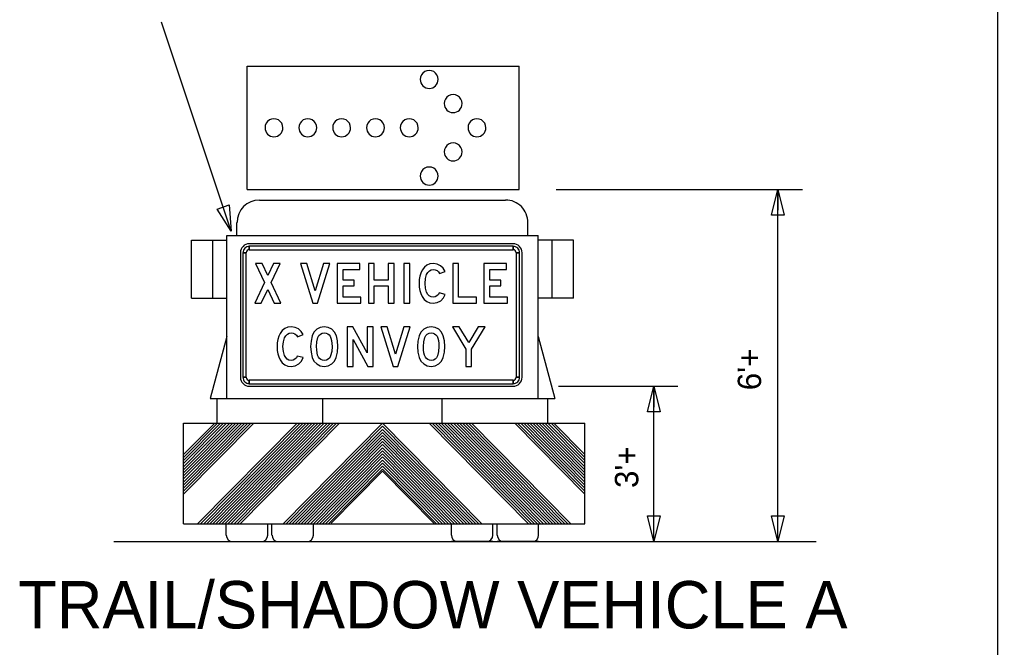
# Model space of a CAD drawing. Extents: x 1416408 to 1429341, y 372694 to 383211.
# Drawn here: x 1427683.6 to 1428099.1, y 374030.4 to 374297 of the extents above; entities that cross this region are included whole.
import ezdxf

# ---------------------------------------------------------------- set-up
doc = ezdxf.new("R2010")
doc.units = 0
doc.layers.add('Working Level 1', color=7, linetype='Continuous')

msp = doc.modelspace()

# ---------------------------------------------------------------- linework, layer by layer
at = {"layer": 'Working Level 1'}
for p, q in [((1428099.08, 374447.3), (1428099.08, 372727.17)), ((1427773.53, 374207.09), (1427743.96, 374295.96)), ((1427780.31, 374277.25), (1427895.86, 374277.25)), ((1427780.31, 374224.87), (1427780.31, 374277.25)), ((1427895.86, 374224.87), (1427895.86, 374277.25)), ((1427780.31, 374224.87), (1427895.86, 374224.87)), ((1427911.54, 374224.87), (1428016.33, 374224.87)), ((1428005.79, 374075.32), (1428005.79, 374224.87)), ((1428005.79, 374224.87), (1428005.79, 374216.1)), ((1427785.52, 374220.38), (1427890.09, 374220.38)), ((1427776.01, 374205.26), (1427776.01, 374210.78)), ((1427899.6, 374205.26), (1427899.6, 374210.78)), ((1427771.7, 374136.16), (1427771.7, 374205.26)), ((1427771.7, 374205.26), (1427903.91, 374205.26)), ((1427903.91, 374136.16), (1427903.91, 374205.26)), ((1427756.62, 374178.75), (1427756.62, 374203.31)), ((1427756.62, 374203.31), (1427771.7, 374203.31)), ((1427765.75, 374178.75), (1427765.75, 374203.31)), ((1427893.36, 374201.79), (1427781.21, 374201.79)), ((1427918.99, 374203.31), (1427903.91, 374203.31)), ((1427909.85, 374178.75), (1427909.85, 374203.31)), ((1427918.99, 374178.75), (1427918.99, 374203.31)), ((1427777.48, 374198.01), (1427777.48, 374145.1)), ((1427778.51, 374198.01), (1427779.97, 374198.01)), ((1427781.21, 374199.27), (1427781.21, 374200.74)), ((1427893.36, 374200.74), (1427893.36, 374199.27)), ((1427894.6, 374198.01), (1427896.06, 374198.01)), ((1427897.1, 374145.1), (1427897.1, 374198.01)), ((1427756.62, 374178.75), (1427771.7, 374178.75)), ((1427918.99, 374178.75), (1427903.91, 374178.75)), ((1427771.7, 374162.48), (1427764.55, 374136.16)), ((1427903.91, 374162.48), (1427911.06, 374136.16)), ((1427779.97, 374145.1), (1427778.51, 374145.1)), ((1427781.21, 374142.37), (1427781.21, 374143.84)), ((1427893.36, 374143.84), (1427893.36, 374142.37)), ((1427896.06, 374145.1), (1427894.6, 374145.1)), ((1427781.21, 374141.32), (1427893.36, 374141.32)), ((1427912.62, 374141.32), (1427963.33, 374141.32)), ((1427953.11, 374075.32), (1427953.11, 374141.32)), ((1427953.11, 374141.32), (1427953.11, 374132.41)), ((1427764.55, 374136.16), (1427911.06, 374136.16)), ((1427767.52, 374125.61), (1427767.52, 374136.16)), ((1427812.44, 374125.61), (1427812.44, 374135.97)), ((1427863.17, 374125.61), (1427863.17, 374135.97)), ((1427908.09, 374125.61), (1427908.09, 374136.16)), ((1427753.33, 374125.61), (1427923.83, 374125.61)), ((1427753.33, 374125.61), (1427923.83, 374125.61)), ((1427753.33, 374125.61), (1427923.83, 374125.61)), ((1427753.33, 374125.61), (1427923.83, 374125.61)), ((1427753.33, 374082.92), (1427753.33, 374125.61)), ((1427753.33, 374112.25), (1427766.55, 374125.61)), ((1427753.33, 374096.71), (1427781.91, 374125.61)), ((1427753.33, 374098.02), (1427780.62, 374125.61)), ((1427753.33, 374099.33), (1427779.33, 374125.61)), ((1427753.33, 374100.62), (1427778.05, 374125.61)), ((1427753.33, 374101.92), (1427776.76, 374125.61)), ((1427753.33, 374103.23), (1427775.46, 374125.61)), ((1427753.33, 374104.52), (1427774.19, 374125.61)), ((1427753.33, 374105.83), (1427772.9, 374125.61)), ((1427753.33, 374107.14), (1427771.6, 374125.61)), ((1427753.33, 374108.44), (1427770.31, 374125.61)), ((1427753.33, 374109.73), (1427769.03, 374125.61)), ((1427753.33, 374111.04), (1427767.74, 374125.61)), ((1427753.33, 374095.41), (1427783.16, 374125.57)), ((1427759.28, 374082.92), (1427801.51, 374125.61)), ((1427760.56, 374082.92), (1427802.79, 374125.61)), ((1427761.86, 374082.92), (1427804.08, 374125.61)), ((1427763.15, 374082.92), (1427805.38, 374125.61)), ((1427764.42, 374082.92), (1427806.65, 374125.61)), ((1427765.72, 374082.92), (1427807.95, 374125.61)), ((1427767.01, 374082.92), (1427809.24, 374125.61)), ((1427768.3, 374082.92), (1427810.53, 374125.61)), ((1427769.58, 374082.92), (1427811.81, 374125.61)), ((1427770.87, 374082.92), (1427813.1, 374125.61)), ((1427772.17, 374082.92), (1427814.39, 374125.61)), ((1427773.44, 374082.92), (1427815.67, 374125.61)), ((1427774.74, 374082.92), (1427816.96, 374125.61)), ((1427776.03, 374082.92), (1427818.24, 374125.59)), ((1427777.31, 374082.92), (1427819.54, 374125.61)), ((1427795.58, 374082.92), (1427837.8, 374125.61)), ((1427796.86, 374082.92), (1427837.8, 374124.31)), ((1427798.15, 374082.92), (1427837.8, 374123)), ((1427880.03, 374082.92), (1427837.8, 374125.61)), ((1427878.68, 374082.99), (1427837.8, 374124.31)), ((1427877.46, 374082.92), (1427837.8, 374123)), ((1427899.84, 374082.92), (1427857.62, 374125.61)), ((1427901.13, 374082.92), (1427858.92, 374125.59)), ((1427902.42, 374082.92), (1427860.19, 374125.61)), ((1427903.72, 374082.92), (1427861.49, 374125.61)), ((1427904.99, 374082.92), (1427862.76, 374125.61)), ((1427906.28, 374082.92), (1427864.06, 374125.61)), ((1427907.58, 374082.92), (1427865.35, 374125.61)), ((1427908.85, 374082.92), (1427866.62, 374125.61)), ((1427910.15, 374082.92), (1427867.92, 374125.61)), ((1427911.44, 374082.92), (1427869.21, 374125.61)), ((1427912.73, 374082.92), (1427870.5, 374125.61)), ((1427914.01, 374082.92), (1427871.78, 374125.61)), ((1427915.3, 374082.92), (1427873.07, 374125.61)), ((1427916.6, 374082.92), (1427874.37, 374125.61)), ((1427917.88, 374082.92), (1427875.65, 374125.61)), ((1427923.83, 374095.41), (1427894, 374125.57)), ((1427923.83, 374096.71), (1427895.24, 374125.61)), ((1427923.83, 374098.02), (1427896.54, 374125.61)), ((1427923.83, 374099.33), (1427897.83, 374125.61)), ((1427923.83, 374100.62), (1427899.11, 374125.61)), ((1427923.83, 374101.92), (1427900.4, 374125.61)), ((1427923.83, 374103.23), (1427901.69, 374125.61)), ((1427923.83, 374104.52), (1427902.97, 374125.61)), ((1427923.83, 374105.83), (1427904.26, 374125.61)), ((1427923.83, 374107.14), (1427905.56, 374125.61)), ((1427923.83, 374108.44), (1427906.85, 374125.61)), ((1427923.83, 374109.73), (1427908.12, 374125.61)), ((1427923.83, 374111.04), (1427909.42, 374125.61)), ((1427923.83, 374112.25), (1427910.61, 374125.61)), ((1427923.83, 374082.92), (1427923.83, 374125.61)), ((1427799.45, 374082.92), (1427837.8, 374121.7)), ((1427800.72, 374082.92), (1427837.8, 374120.41)), ((1427802.02, 374082.92), (1427837.8, 374119.1)), ((1427803.31, 374082.92), (1427837.8, 374117.79)), ((1427876.17, 374082.92), (1427837.8, 374121.7)), ((1427874.9, 374082.92), (1427837.8, 374120.41)), ((1427873.6, 374082.92), (1427837.8, 374119.1)), ((1427872.31, 374082.92), (1427837.8, 374117.79)), ((1427804.58, 374082.92), (1427837.8, 374116.5)), ((1427805.88, 374082.92), (1427837.8, 374115.19)), ((1427807.17, 374082.92), (1427837.8, 374113.89)), ((1427871.03, 374082.92), (1427837.8, 374116.5)), ((1427869.74, 374082.92), (1427837.8, 374115.19)), ((1427868.45, 374082.92), (1427837.8, 374113.89)), ((1427808.46, 374082.92), (1427837.8, 374112.58)), ((1427809.74, 374082.92), (1427837.8, 374111.29)), ((1427811.03, 374082.92), (1427837.8, 374109.98)), ((1427867.15, 374082.92), (1427837.8, 374112.58)), ((1427865.88, 374082.92), (1427837.8, 374111.29)), ((1427864.58, 374082.92), (1427837.8, 374109.98)), ((1427812.33, 374082.92), (1427837.8, 374108.67)), ((1427813.6, 374082.92), (1427837.8, 374107.39)), ((1427814.89, 374082.92), (1427837.8, 374106.09)), ((1427863.29, 374082.92), (1427837.8, 374108.67)), ((1427862.02, 374082.92), (1427837.8, 374107.39)), ((1427860.72, 374082.92), (1427837.8, 374106.09)), ((1427815.97, 374083.16), (1427837.8, 374105.24)), ((1427859.88, 374082.92), (1427837.8, 374105.24)), ((1427753.33, 374082.92), (1427923.83, 374082.92)), ((1427753.33, 374082.92), (1427923.83, 374082.92)), ((1427753.33, 374082.92), (1427923.83, 374082.92)), ((1427753.33, 374082.92), (1427923.83, 374082.92)), ((1427771.45, 374078.08), (1427771.45, 374082.92)), ((1427789.06, 374078.08), (1427789.06, 374082.92)), ((1427790.88, 374078.08), (1427790.88, 374082.92)), ((1427808.5, 374078.08), (1427808.5, 374082.92)), ((1427867.11, 374078.08), (1427867.11, 374082.92)), ((1427884.72, 374078.08), (1427884.72, 374082.92)), ((1427886.55, 374078.08), (1427886.55, 374082.92)), ((1427904.16, 374078.08), (1427904.16, 374082.92)), ((1427723.72, 374075.32), (1428022.01, 374075.32)), ((1427771.45, 374075.32), (1427789.06, 374075.32)), ((1427771.45, 374075.32), (1427789.06, 374075.32)), ((1427771.45, 374075.32), (1427789.06, 374075.32)), ((1427771.45, 374075.32), (1427789.06, 374075.32)), ((1427790.88, 374075.32), (1427808.5, 374075.32)), ((1427790.88, 374075.32), (1427808.5, 374075.32)), ((1427790.88, 374075.32), (1427808.5, 374075.32)), ((1427790.88, 374075.32), (1427808.5, 374075.32)), ((1427884.72, 374075.32), (1427867.11, 374075.32)), ((1427884.72, 374075.32), (1427867.11, 374075.32)), ((1427884.72, 374075.32), (1427867.11, 374075.32)), ((1427884.72, 374075.32), (1427867.11, 374075.32)), ((1427904.16, 374075.32), (1427886.55, 374075.32)), ((1427904.16, 374075.32), (1427886.55, 374075.32)), ((1427904.16, 374075.32), (1427886.55, 374075.32)), ((1427904.16, 374075.32), (1427886.55, 374075.32))]:
    msp.add_line(p, q, dxfattribs=at)
for points in [[(1428003.1, 374213.98), (1428005.79, 374224.87), (1428008.48, 374213.98)], [(1427772.65, 374218.28), (1427773.53, 374207.09), (1427767.55, 374216.54)], [(1427778.51, 374198.01), (1427778.51, 374145.1), (1427779.97, 374145.1), (1427779.97, 374198.01), (1427778.51, 374198.01)], [(1427893.36, 374200.74), (1427781.21, 374200.74), (1427781.21, 374199.27), (1427893.36, 374199.27), (1427893.36, 374200.74)], [(1427896.06, 374145.1), (1427896.06, 374198.01), (1427894.6, 374198.01), (1427894.6, 374145.1), (1427896.06, 374145.1)], [(1427794.64, 374176.6), (1427790.5, 374185.39), (1427794.29, 374193.39), (1427791.52, 374193.39), (1427789.11, 374188.32), (1427786.72, 374193.39), (1427783.94, 374193.39), (1427787.72, 374185.37), (1427783.55, 374176.6), (1427786.33, 374176.6), (1427789.1, 374182.43), (1427791.86, 374176.6)], [(1427815.39, 374193.39), (1427812.77, 374193.39), (1427809.2, 374181.79), (1427805.64, 374193.39), (1427803.02, 374193.39), (1427808.17, 374176.6), (1427810.23, 374176.6)], [(1427828.64, 374179.13), (1427821.1, 374179.13), (1427821.1, 374183.89), (1427825.8, 374183.89), (1427825.8, 374186.42), (1427821.1, 374186.42), (1427821.1, 374190.86), (1427828.13, 374190.86), (1427828.13, 374193.39), (1427818.59, 374193.39), (1427818.59, 374176.6), (1427828.64, 374176.6)], [(1427842.8, 374176.6), (1427842.8, 374193.39), (1427840.3, 374193.39), (1427840.3, 374186.42), (1427834.34, 374186.42), (1427834.34, 374193.39), (1427831.83, 374193.39), (1427831.83, 374176.6), (1427834.34, 374176.6), (1427834.34, 374183.89), (1427840.3, 374183.89), (1427840.3, 374176.6)], [(1427849.4, 374176.6), (1427849.4, 374193.39), (1427846.89, 374193.39), (1427846.89, 374176.6)], [(1427864.47, 374180.32), (1427861.96, 374180.97), (1427861.59, 374180.23), (1427860.98, 374179.65), (1427860.2, 374179.26), (1427859.33, 374179.13), (1427858.46, 374179.26), (1427857.71, 374179.67), (1427857.08, 374180.33), (1427856.57, 374181.27), (1427856.06, 374182.99), (1427855.89, 374184.99), (1427856.06, 374187), (1427856.59, 374188.73), (1427857.11, 374189.66), (1427857.76, 374190.32), (1427858.52, 374190.72), (1427859.42, 374190.86), (1427860.24, 374190.74), (1427861, 374190.39), (1427861.63, 374189.84), (1427862.06, 374189.14), (1427864.47, 374190.09), (1427863.66, 374191.44), (1427862.47, 374192.49), (1427861.03, 374193.16), (1427859.45, 374193.39), (1427857.99, 374193.22), (1427856.72, 374192.69), (1427855.63, 374191.81), (1427854.72, 374190.59), (1427854.13, 374189.38), (1427853.71, 374188.04), (1427853.47, 374186.58), (1427853.38, 374185), (1427853.46, 374183.42), (1427853.71, 374181.97), (1427854.12, 374180.64), (1427854.7, 374179.43), (1427855.59, 374178.19), (1427856.67, 374177.3), (1427857.93, 374176.77), (1427859.37, 374176.6), (1427861.06, 374176.85), (1427862.58, 374177.63), (1427863.76, 374178.82)], [(1427877.7, 374176.6), (1427877.7, 374179.13), (1427870.17, 374179.13), (1427870.17, 374193.39), (1427867.66, 374193.39), (1427867.66, 374176.6)], [(1427890.94, 374179.13), (1427883.41, 374179.13), (1427883.41, 374183.89), (1427888.11, 374183.89), (1427888.11, 374186.42), (1427883.41, 374186.42), (1427883.41, 374190.86), (1427890.44, 374190.86), (1427890.44, 374193.39), (1427880.9, 374193.39), (1427880.9, 374176.6), (1427890.94, 374176.6)], [(1427804.11, 374153.45), (1427801.6, 374154.09), (1427801.23, 374153.35), (1427800.62, 374152.77), (1427799.84, 374152.38), (1427798.98, 374152.26), (1427798.1, 374152.39), (1427797.35, 374152.79), (1427796.72, 374153.46), (1427796.21, 374154.39), (1427795.7, 374156.12), (1427795.53, 374158.12), (1427795.7, 374160.13), (1427796.23, 374161.86), (1427796.76, 374162.78), (1427797.4, 374163.45), (1427798.17, 374163.85), (1427799.06, 374163.98), (1427799.89, 374163.86), (1427800.64, 374163.52), (1427801.27, 374162.97), (1427801.7, 374162.26), (1427804.11, 374163.22), (1427803.3, 374164.57), (1427802.12, 374165.62), (1427800.68, 374166.29), (1427799.1, 374166.52), (1427797.63, 374166.34), (1427796.36, 374165.82), (1427795.27, 374164.94), (1427794.36, 374163.72), (1427793.77, 374162.5), (1427793.36, 374161.17), (1427793.11, 374159.71), (1427793.03, 374158.13), (1427793.1, 374156.55), (1427793.35, 374155.09), (1427793.76, 374153.76), (1427794.35, 374152.55), (1427795.23, 374151.31), (1427796.31, 374150.43), (1427797.57, 374149.89), (1427799.01, 374149.72), (1427800.7, 374149.98), (1427802.22, 374150.75), (1427803.41, 374151.95)], [(1427818.9, 374158.13), (1427818.73, 374160.52), (1427818.22, 374162.77), (1427817.48, 374164.28), (1427816.29, 374165.48), (1427814.78, 374166.25), (1427813.09, 374166.52), (1427811.4, 374166.25), (1427809.91, 374165.48), (1427808.72, 374164.28), (1427807.98, 374162.75), (1427807.47, 374160.51), (1427807.3, 374158.13), (1427807.47, 374155.75), (1427807.98, 374153.5), (1427808.72, 374151.97), (1427809.91, 374150.77), (1427811.4, 374149.98), (1427813.09, 374149.72), (1427814.78, 374149.98), (1427816.28, 374150.75), (1427817.46, 374151.95), (1427818.21, 374153.47), (1427818.72, 374155.72)], [(1427816.39, 374158.12), (1427816.24, 374156.08), (1427815.8, 374154.18), (1427815.4, 374153.39), (1427814.78, 374152.78), (1427814, 374152.38), (1427813.11, 374152.26), (1427812.33, 374152.34), (1427811.66, 374152.62), (1427811.09, 374153.08), (1427810.63, 374153.72), (1427810.27, 374154.54), (1427810.01, 374155.55), (1427809.86, 374156.74), (1427809.81, 374158.12), (1427809.96, 374160.15), (1427810.4, 374162.04), (1427810.79, 374162.83), (1427811.42, 374163.45), (1427812.2, 374163.85), (1427813.11, 374163.98), (1427813.88, 374163.89), (1427814.54, 374163.61), (1427815.11, 374163.16), (1427815.57, 374162.52), (1427815.93, 374161.69), (1427816.19, 374160.68), (1427816.34, 374159.49)], [(1427833.85, 374149.72), (1427833.85, 374166.52), (1427831.34, 374166.52), (1427831.34, 374155.47), (1427825.29, 374166.52), (1427822.88, 374166.52), (1427822.88, 374149.72), (1427825.39, 374149.72), (1427825.39, 374161.12), (1427831.64, 374149.72)], [(1427849.53, 374166.52), (1427846.9, 374166.52), (1427843.34, 374154.91), (1427839.78, 374166.52), (1427837.16, 374166.52), (1427842.3, 374149.72), (1427844.37, 374149.72)], [(1427864.33, 374158.13), (1427864.16, 374160.52), (1427863.65, 374162.77), (1427862.91, 374164.28), (1427861.72, 374165.48), (1427860.21, 374166.25), (1427858.52, 374166.52), (1427856.83, 374166.25), (1427855.34, 374165.48), (1427854.15, 374164.28), (1427853.41, 374162.75), (1427852.9, 374160.51), (1427852.73, 374158.13), (1427852.9, 374155.75), (1427853.41, 374153.5), (1427854.15, 374151.97), (1427855.34, 374150.77), (1427856.83, 374149.98), (1427858.52, 374149.72), (1427860.21, 374149.98), (1427861.7, 374150.75), (1427862.89, 374151.95), (1427863.64, 374153.47), (1427864.15, 374155.72)], [(1427861.82, 374158.12), (1427861.67, 374156.08), (1427861.23, 374154.18), (1427860.83, 374153.39), (1427860.21, 374152.78), (1427859.43, 374152.38), (1427858.54, 374152.26), (1427857.76, 374152.34), (1427857.09, 374152.62), (1427856.52, 374153.08), (1427856.06, 374153.72), (1427855.7, 374154.54), (1427855.44, 374155.55), (1427855.29, 374156.74), (1427855.24, 374158.12), (1427855.39, 374160.15), (1427855.83, 374162.04), (1427856.22, 374162.83), (1427856.85, 374163.45), (1427857.63, 374163.85), (1427858.54, 374163.98), (1427859.31, 374163.89), (1427859.97, 374163.61), (1427860.53, 374163.16), (1427861, 374162.52), (1427861.36, 374161.69), (1427861.62, 374160.68), (1427861.77, 374159.49)], [(1427881.45, 374166.52), (1427878.51, 374166.52), (1427874.44, 374159.81), (1427870.45, 374166.52), (1427867.53, 374166.52), (1427873.17, 374157.08), (1427873.17, 374149.72), (1427875.68, 374149.72), (1427875.68, 374157.01)], [(1427781.21, 374142.37), (1427893.36, 374142.37), (1427893.36, 374143.84), (1427781.21, 374143.84), (1427781.21, 374142.37)], [(1427950.41, 374130.44), (1427953.11, 374141.32), (1427955.8, 374130.44)], [(1427955.8, 374086.2), (1427953.11, 374075.32), (1427950.41, 374086.2)], [(1428008.48, 374086.2), (1428005.79, 374075.32), (1428003.1, 374086.2)]]:
    msp.add_lwpolyline(points, close=True, dxfattribs=at)
for centre, major_axis, start_param, end_param in [((1427857.68, 374271.59), (0, 3.84), 4.712389, 7.853982), ((1427857.68, 374271.59), (0, 3.84), 1.570797, 4.712389), ((1427867.82, 374261.33), (0, 3.84), 4.712389, 7.853982), ((1427867.82, 374261.33), (0, 3.84), 1.570797, 4.712389), ((1427791.71, 374251.06), (0, 3.84), 4.712389, 7.853982), ((1427806.08, 374251.06), (0, 3.84), 4.712389, 7.853982), ((1427820.46, 374251.06), (0, 3.84), 4.712389, 7.853982), ((1427834.83, 374251.06), (0, 3.84), 4.712389, 7.853982), ((1427849.2, 374251.06), (0, 3.84), 4.712389, 7.853982), ((1427877.95, 374251.06), (0, 3.84), 4.712389, 7.853982), ((1427791.71, 374251.06), (0, 3.84), 1.570797, 4.712389), ((1427806.08, 374251.06), (0, 3.84), 1.570797, 4.712389), ((1427820.46, 374251.06), (0, 3.84), 1.570797, 4.712389), ((1427834.83, 374251.06), (0, 3.84), 1.570797, 4.712389), ((1427849.2, 374251.06), (0, 3.84), 1.570797, 4.712389), ((1427877.95, 374251.06), (0, 3.84), 1.570797, 4.712389), ((1427867.82, 374240.82), (0, 3.84), 4.712389, 7.853982), ((1427867.82, 374240.82), (0, 3.84), 1.570797, 4.712389), ((1427857.68, 374230.57), (0, 3.84), 4.712389, 7.853982), ((1427857.68, 374230.57), (0, 3.84), 1.570797, 4.712389), ((1427785.52, 374210.78), (0, 9.61), 6.283185, 7.853981), ((1427890.09, 374210.78), (0, 9.61), 4.712389, 6.283186), ((1427781.21, 374198.01), (0, 3.78), 0.000004, 1.570794), ((1427893.36, 374198.01), (0, 3.78), 4.712389, 6.283189), ((1427781.21, 374198.01), (0, 2.73), 0.000004, 1.570794), ((1427781.21, 374198.01), (0, 1.26), 0.000004, 1.570794), ((1427893.36, 374198.01), (0, 2.73), 4.712389, 6.283189), ((1427893.36, 374198.01), (0, 1.26), 4.712389, 6.283189), ((1427781.21, 374145.1), (0, 3.78), 1.570794, 3.141594), ((1427781.21, 374145.1), (0, 2.73), 1.570794, 3.141594), ((1427781.21, 374145.1), (0, 1.26), 1.570794, 3.141594), ((1427893.36, 374145.1), (0, 3.78), 3.141594, 4.712394), ((1427893.36, 374145.1), (0, 2.73), 3.141594, 4.712394), ((1427893.36, 374145.1), (0, 1.26), 3.141594, 4.712394), ((1427774.18, 374078.08), (0, -2.76), 4.712389, 6.283185), ((1427786.33, 374078.08), (0, 2.76), 3.141593, 4.712389), ((1427793.62, 374078.08), (0, -2.76), 4.712389, 6.283185), ((1427805.77, 374078.08), (0, 2.76), 3.141593, 4.712389), ((1427869.84, 374078.08), (0, -2.76), 4.712389, 6.283185), ((1427881.99, 374078.08), (0, 2.76), 3.141593, 4.712389), ((1427889.28, 374078.08), (0, -2.76), 4.712389, 6.283185), ((1427901.43, 374078.08), (0, 2.76), 3.141593, 4.712389)]:
    msp.add_ellipse(centre, major_axis=major_axis, ratio=0.989089, start_param=start_param, end_param=end_param, dxfattribs=at)

# ---------------------------------------------------------------- texts
for s, p in [("6'+", (1427998.67, 374139.61)), ("3'+", (1427946.5, 374098.08))]:
    msp.add_text(s, height=9.937, rotation=90, dxfattribs=at).set_placement(p)
msp.add_text('TRAIL/SHADOW VEHICLE A', height=20.0929, dxfattribs=at).set_placement((1427683.03, 374038.48))

doc.saveas('drawing.dxf')
